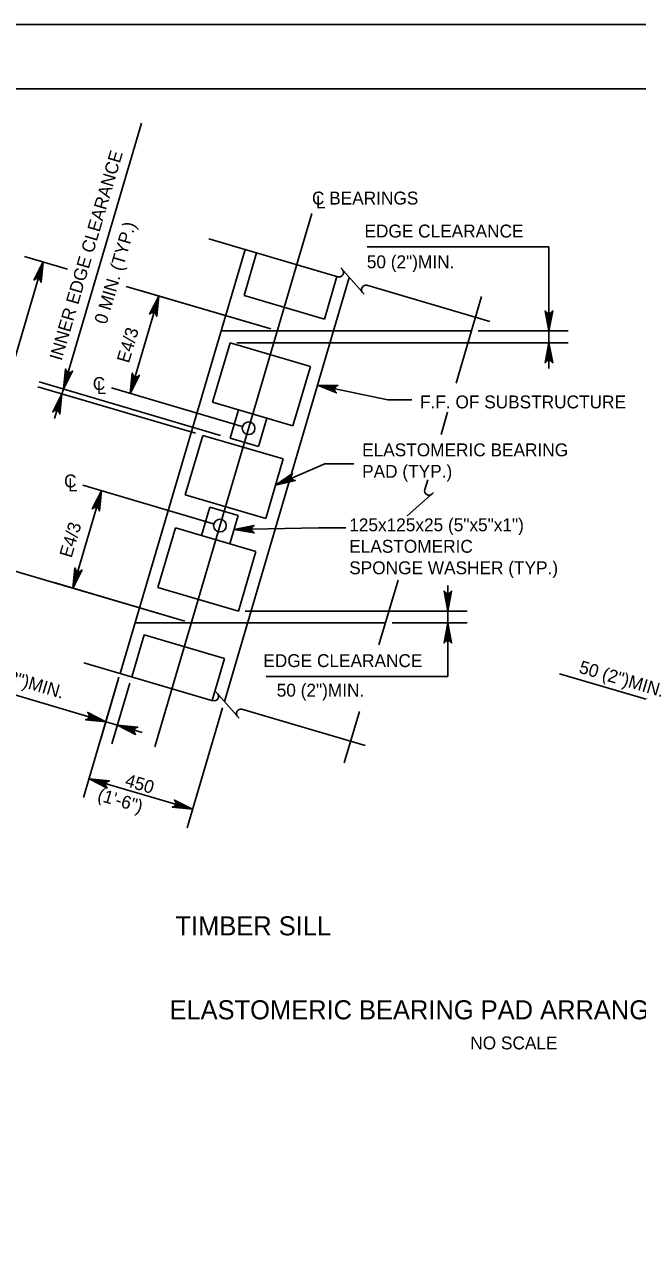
# Model space of a CAD drawing. Extents: x 638268 to 640277, y 295465 to 298435.
# Drawn here: x 639790.3 to 639932.9, y 298150.4 to 298435.5 of the extents above; entities that cross this region are included whole.
import ezdxf

# ---------------------------------------------------------------- set-up
doc = ezdxf.new("R2010")
doc.units = 0
for name, color, linetype in [('2', 7, 'Continuous'), ('3', 7, 'Continuous'), ('4', 7, 'Continuous'), ('7', 7, 'Continuous'), ('PLT-BNDY', 7, 'Continuous')]:
    doc.layers.add(name, color=color, linetype=linetype)

msp = doc.modelspace()

# ---------------------------------------------------------------- linework, layer by layer
at = {"layer": '2'}
msp.add_line((639316.46, 298420.46), (640102.46, 298420.46), dxfattribs=at)
at = {"layer": '3'}
for p, q in [((639833.22, 298385.58), (639863.23, 298376.74)), ((639812.58, 298284.45), (639841.64, 298383.1)), ((639774.66, 298312.22), (639794.68, 298380.2)), ((639800.32, 298378.54), (639790.36, 298381.47)), ((639863.93, 298378.81), (639869.34, 298372.67)), ((639847.64, 298364.6), (639814.01, 298374.5)), ((639865.89, 298376.59), (639836.83, 298277.94)), ((639869.94, 298374.77), (639898.62, 298366.32)), ((639841.42, 298372.42), (639860.11, 298366.91)), ((639896.68, 298372.12), (639890.74, 298351.98)), ((639836.06, 298364.16), (639894.33, 298364.16)), ((639838.17, 298361.4), (639856.86, 298355.9)), ((639835.93, 298339.83), (639793.74, 298352.26)), ((639830.12, 298340.34), (639793.42, 298351.16)), ((639834.09, 298347.56), (639852.79, 298342.05)), ((639840.14, 298345.77), (639846.74, 298343.83)), ((639888.77, 298345.26), (639887.23, 298340.03)), ((639831.82, 298339.84), (639850.51, 298334.34)), ((639838.19, 298339.17), (639844.8, 298337.22)), ((639884.13, 298329.51), (639883.46, 298327.24)), ((639827.74, 298326), (639846.44, 298320.49)), ((639885.52, 298326.55), (639879.39, 298321.13)), ((639833.46, 298323.12), (639840.07, 298321.17)), ((639825.47, 298318.29), (639844.17, 298312.78)), ((639831.51, 298316.51), (639838.12, 298314.56)), ((639827.62, 298296.62), (639770.34, 298313.49)), ((639877.23, 298306.11), (639872.8, 298291.07)), ((639821.39, 298304.44), (639840.09, 298298.93)), ((639816.04, 298296.18), (639874.31, 298296.18)), ((639818.15, 298293.42), (639836.84, 298287.92)), ((639804.17, 298286.93), (639834.18, 298278.09)), ((639834.87, 298280.16), (639840.28, 298274.02)), ((639840.89, 298276.12), (639869.56, 298267.67)), ((639868.25, 298275.6), (639864.71, 298263.61))]:
    msp.add_line(p, q, dxfattribs=at)
msp.add_lwpolyline([(639793.35, 298377.46), (639794.31, 298377.18), (639794.68, 298380.2)], close=True, dxfattribs=at)
for centre, start, end in [((639863.52, 298377.72), 253.588, 43.588), ((639869.75, 298373.76), 78.9166, 221.4552), ((639884.44, 298326.95), 163.588, 313.588), ((639834.47, 298279.08), 253.588, 43.588), ((639840.69, 298275.11), 78.9166, 221.4552)]:
    msp.add_arc(centre, 1.02, start, end, dxfattribs=at)
at = {"layer": '4'}
for p, q in [((639800.22, 298353.48), (639817.59, 298412.47)), ((639820.63, 298267.37), (639857.18, 298391.45)), ((639870.07, 298383.7), (639912.34, 298383.7)), ((639912.34, 298367.16), (639912.34, 298383.7)), ((639814.91, 298349.61), (639821.59, 298372.27)), ((639847.64, 298364.6), (639817.27, 298373.54)), ((639895.89, 298364.16), (639916.84, 298364.16)), ((639912.34, 298361.4), (639912.34, 298364.16)), ((639839.73, 298361.4), (639916.84, 298361.4)), ((639912.34, 298358.4), (639912.34, 298355.4)), ((639799.04, 298349.5), (639799.37, 298350.6)), ((639840.97, 298341.94), (639810.6, 298350.89)), ((639798.2, 298346.62), (639797.35, 298343.74)), ((639874.89, 298348.09), (639880.42, 298348.09)), ((639860.08, 298333.18), (639866.93, 298333.18)), ((639801.56, 298304.3), (639808.24, 298326.95)), ((639834.29, 298319.28), (639803.92, 298328.22)), ((639858.72, 298318.32), (639865.09, 298318.32)), ((639827.62, 298296.62), (639797.25, 298305.57)), ((639888.81, 298301.93), (639888.81, 298304.93)), ((639841.65, 298298.93), (639893.31, 298298.93)), ((639888.81, 298298.93), (639888.81, 298296.18)), ((639875.87, 298296.18), (639893.31, 298296.18)), ((639888.81, 298293.18), (639888.81, 298283.71)), ((639812.31, 298283.53), (639804.08, 298255.59)), ((639812.14, 298282.96), (639808, 298268.88)), ((639846.55, 298283.71), (639888.81, 298283.71)), ((639952.69, 298273.2), (639914.76, 298284.37)), ((639809.27, 298273.2), (639777.97, 298282.42)), ((639814.83, 298282.16), (639810.69, 298268.09)), ((639836.39, 298276.44), (639828.16, 298248.5)), ((639811.96, 298272.4), (639809.27, 298273.2)), ((639811.96, 298272.4), (639817.71, 298270.71)), ((639829.43, 298252.81), (639805.35, 298259.91))]:
    msp.add_line(p, q, dxfattribs=at)
for points in [[(639794.68, 298380.2), (639794.2, 298375.48), (639794.06, 298375.9), (639793.82, 298376.16), (639793.53, 298376.3), (639793.22, 298376.34), (639792.86, 298376.25), (639792.53, 298375.98), (639794.68, 298380.2), (639792.86, 298376.25), (639793.22, 298376.34), (639794.68, 298380.2), (639793.53, 298376.3), (639793.82, 298376.16), (639794.68, 298380.2), (639794.06, 298375.9)], [(639821.59, 298372.27), (639821.11, 298367.56), (639820.97, 298367.97), (639820.73, 298368.24), (639820.44, 298368.37), (639820.13, 298368.41), (639819.77, 298368.32), (639819.43, 298368.05), (639821.59, 298372.27), (639819.77, 298368.32), (639820.13, 298368.41), (639821.59, 298372.27), (639820.44, 298368.37), (639820.73, 298368.24), (639821.59, 298372.27), (639820.97, 298367.97)], [(639912.34, 298364.16), (639911.46, 298368.82), (639911.71, 298368.46), (639912.02, 298368.27), (639912.34, 298368.22), (639912.65, 298368.27), (639912.96, 298368.46), (639913.21, 298368.82), (639912.34, 298364.16), (639912.96, 298368.46), (639912.65, 298368.27), (639912.34, 298364.16), (639912.34, 298368.22), (639912.02, 298368.27), (639912.34, 298364.16), (639911.71, 298368.46)], [(639912.34, 298361.4), (639913.21, 298356.74), (639912.96, 298357.1), (639912.65, 298357.29), (639912.34, 298357.34), (639912.02, 298357.29), (639911.71, 298357.1), (639911.46, 298356.74), (639912.34, 298361.4), (639911.71, 298357.1), (639912.02, 298357.29), (639912.34, 298361.4), (639912.34, 298357.34), (639912.65, 298357.29), (639912.34, 298361.4), (639912.96, 298357.1)], [(639799.37, 298350.6), (639799.85, 298355.32), (639799.99, 298354.9), (639800.23, 298354.64), (639800.52, 298354.5), (639800.83, 298354.46), (639801.18, 298354.55), (639801.53, 298354.82), (639799.37, 298350.6), (639801.18, 298354.55), (639800.83, 298354.46), (639799.37, 298350.6), (639800.52, 298354.5), (639800.23, 298354.64), (639799.37, 298350.6), (639799.99, 298354.9)], [(639814.91, 298349.61), (639815.39, 298354.33), (639815.53, 298353.92), (639815.78, 298353.65), (639816.06, 298353.51), (639816.38, 298353.47), (639816.73, 298353.56), (639817.07, 298353.84), (639814.91, 298349.61), (639816.73, 298353.56), (639816.38, 298353.47), (639814.91, 298349.61), (639816.06, 298353.51), (639815.78, 298353.65), (639814.91, 298349.61), (639815.53, 298353.92)], [(639858.51, 298351.54), (639874.89, 298348.09)], [(639858.51, 298351.54), (639863.25, 298351.44), (639862.84, 298351.27), (639862.6, 298351), (639862.48, 298350.7), (639862.47, 298350.39), (639862.59, 298350.04), (639862.89, 298349.73), (639858.51, 298351.54), (639862.59, 298350.04), (639862.47, 298350.39), (639858.51, 298351.54), (639862.48, 298350.7), (639862.6, 298351), (639858.51, 298351.54), (639862.84, 298351.27)], [(639799.04, 298349.5), (639798.56, 298344.78), (639798.43, 298345.2), (639798.18, 298345.46), (639797.9, 298345.6), (639797.58, 298345.64), (639797.23, 298345.55), (639796.89, 298345.27), (639799.04, 298349.5), (639797.23, 298345.55), (639797.58, 298345.64), (639799.04, 298349.5), (639797.9, 298345.6), (639798.18, 298345.46), (639799.04, 298349.5), (639798.43, 298345.2)], [(639848.73, 298328.28), (639860.24, 298333.25)], [(639848.73, 298328.28), (639852.67, 298330.93), (639852.44, 298330.56), (639852.39, 298330.2), (639852.46, 298329.9), (639852.64, 298329.63), (639852.93, 298329.42), (639853.36, 298329.33), (639848.73, 298328.28), (639852.93, 298329.42), (639852.64, 298329.63), (639848.73, 298328.28), (639852.46, 298329.9), (639852.39, 298330.2), (639848.73, 298328.28), (639852.44, 298330.56)], [(639808.24, 298326.95), (639807.76, 298322.24), (639807.62, 298322.65), (639807.38, 298322.92), (639807.09, 298323.06), (639806.78, 298323.09), (639806.43, 298323), (639806.09, 298322.73), (639808.24, 298326.95), (639806.43, 298323), (639806.78, 298323.09), (639808.24, 298326.95), (639807.09, 298323.06), (639807.38, 298322.92), (639808.24, 298326.95), (639807.62, 298322.65)], [(639839.11, 298317.92), (639843.75, 298318.89), (639843.4, 298318.63), (639843.22, 298318.32), (639843.18, 298318), (639843.23, 298317.69), (639843.43, 298317.38), (639843.79, 298317.14), (639839.11, 298317.92), (639843.43, 298317.38), (639843.23, 298317.69), (639839.11, 298317.92), (639843.18, 298318), (639843.22, 298318.32), (639839.11, 298317.92), (639843.4, 298318.63)], [(639839.11, 298317.92), (639858.72, 298318.32)], [(639801.56, 298304.3), (639802.04, 298309.01), (639802.18, 298308.6), (639802.43, 298308.33), (639802.71, 298308.19), (639803.03, 298308.16), (639803.38, 298308.25), (639803.72, 298308.52), (639801.56, 298304.3), (639803.38, 298308.25), (639803.03, 298308.16), (639801.56, 298304.3), (639802.71, 298308.19), (639802.43, 298308.33), (639801.56, 298304.3), (639802.18, 298308.6)], [(639888.81, 298298.93), (639887.94, 298303.6), (639888.19, 298303.24), (639888.5, 298303.05), (639888.81, 298303), (639889.13, 298303.05), (639889.44, 298303.24), (639889.69, 298303.6), (639888.81, 298298.93), (639889.44, 298303.24), (639889.13, 298303.05), (639888.81, 298298.93), (639888.81, 298303), (639888.5, 298303.05), (639888.81, 298298.93), (639888.19, 298303.24)], [(639888.81, 298296.18), (639889.69, 298291.52), (639889.44, 298291.88), (639889.13, 298292.06), (639888.81, 298292.12), (639888.5, 298292.06), (639888.19, 298291.88), (639887.94, 298291.52), (639888.81, 298296.18), (639888.19, 298291.88), (639888.5, 298292.06), (639888.81, 298296.18), (639888.81, 298292.12), (639889.13, 298292.06), (639888.81, 298296.18), (639889.44, 298291.88)], [(639809.27, 298273.2), (639804.55, 298273.67), (639804.96, 298273.81), (639805.23, 298274.06), (639805.37, 298274.34), (639805.41, 298274.66), (639805.32, 298275.01), (639805.04, 298275.35), (639809.27, 298273.2), (639805.32, 298275.01), (639805.41, 298274.66), (639809.27, 298273.2), (639805.37, 298274.34), (639805.23, 298274.06), (639809.27, 298273.2), (639804.96, 298273.81)], [(639811.96, 298272.4), (639816.67, 298271.92), (639816.26, 298271.79), (639815.99, 298271.54), (639815.85, 298271.26), (639815.82, 298270.94), (639815.91, 298270.59), (639816.18, 298270.25), (639811.96, 298272.4), (639815.91, 298270.59), (639815.82, 298270.94), (639811.96, 298272.4), (639815.85, 298271.26), (639815.99, 298271.54), (639811.96, 298272.4), (639816.26, 298271.79)], [(639805.35, 298259.91), (639810.07, 298259.43), (639809.65, 298259.29), (639809.39, 298259.04), (639809.25, 298258.76), (639809.21, 298258.44), (639809.3, 298258.09), (639809.58, 298257.75), (639805.35, 298259.91), (639809.3, 298258.09), (639809.21, 298258.44), (639805.35, 298259.91), (639809.25, 298258.76), (639809.39, 298259.04), (639805.35, 298259.91), (639809.65, 298259.29)], [(639829.43, 298252.81), (639824.71, 298253.29), (639825.13, 298253.43), (639825.39, 298253.68), (639825.53, 298253.96), (639825.57, 298254.28), (639825.48, 298254.63), (639825.2, 298254.97), (639829.43, 298252.81), (639825.48, 298254.63), (639825.57, 298254.28), (639829.43, 298252.81), (639825.53, 298253.96), (639825.39, 298253.68), (639829.43, 298252.81), (639825.13, 298253.43)]]:
    msp.add_lwpolyline(points, dxfattribs=at)
for points in [[(639820.26, 298369.54), (639821.22, 298369.25), (639821.59, 298372.27)], [(639911.84, 298367.16), (639912.84, 298367.16), (639912.34, 298364.16)], [(639911.84, 298358.4), (639912.84, 298358.4), (639912.34, 298361.4)], [(639799.74, 298353.62), (639800.7, 298353.34), (639799.37, 298350.6)], [(639815.28, 298352.63), (639816.24, 298352.35), (639814.91, 298349.61)], [(639858.51, 298351.54), (639861.39, 298350.68), (639861.49, 298351.17)], [(639797.72, 298346.76), (639798.68, 298346.48), (639799.04, 298349.5)], [(639848.73, 298328.28), (639851.59, 298329.24), (639851.39, 298329.7)], [(639806.91, 298324.22), (639807.87, 298323.93), (639808.24, 298326.95)], [(639801.93, 298307.31), (639802.89, 298307.03), (639801.56, 298304.29)], [(639888.31, 298301.93), (639889.31, 298301.93), (639888.81, 298298.93)], [(639888.31, 298293.18), (639889.31, 298293.18), (639888.81, 298296.18)], [(639806.53, 298274.52), (639806.25, 298273.56), (639809.27, 298273.2)], [(639814.98, 298272.04), (639814.69, 298271.08), (639811.96, 298272.4)], [(639808.37, 298259.54), (639808.09, 298258.58), (639805.35, 298259.91)], [(639826.69, 298254.14), (639826.41, 298253.18), (639829.43, 298252.81)]]:
    msp.add_lwpolyline(points, close=True, dxfattribs=at)
at = {"layer": '7'}
for p, q in [((639841.42, 298372.42), (639844.33, 298382.31)), ((639860.11, 298366.91), (639863.02, 298376.8)), ((639834.09, 298347.56), (639838.17, 298361.4)), ((639852.79, 298342.05), (639856.86, 298355.9)), ((639838.19, 298339.17), (639840.14, 298345.77)), ((639844.8, 298337.22), (639846.74, 298343.83)), ((639827.74, 298326), (639831.82, 298339.84)), ((639846.44, 298320.49), (639850.51, 298334.34)), ((639831.51, 298316.51), (639833.46, 298323.12)), ((639838.12, 298314.56), (639840.07, 298321.17)), ((639821.39, 298304.44), (639825.47, 298318.29)), ((639840.09, 298298.93), (639844.17, 298312.78)), ((639815.27, 298283.66), (639818.15, 298293.42)), ((639833.97, 298278.16), (639836.84, 298287.92))]:
    msp.add_line(p, q, dxfattribs=at)
for centre in [(639842.47, 298341.5), (639835.79, 298318.84)]:
    msp.add_circle(centre, 1.48, dxfattribs=at)
at = {"layer": 'PLT-BNDY'}
msp.add_lwpolyline([(639276.46, 298435.46), (640117.46, 298435.46), (640117.46, 297841.46), (639276.46, 297841.46)], close=True, dxfattribs=at)

# ---------------------------------------------------------------- texts
at = {"layer": '3'}
for s, p in [('TIMBER SILL', (639825.46, 298223.48)), ('ELASTOMERIC BEARING PAD ARRANGEMENTS', (639824.06, 298203.94))]:
    msp.add_text(s, height=4.4292, dxfattribs=at).set_placement(p)
at = {"layer": '4'}
for s, rotation, p in [('INNER EDGE CLEARANCE', 73.588, (639798.95, 298357.05)), ('0 MIN. (TYP.)', 73.588, (639809.38, 298365.51)), ('E4/3', 73.588, (639814.62, 298356.49)), ('E4/3', 73.588, (639801.27, 298311.17)), ('50 (2")MIN.', 343.588, (639779.54, 298284.27)), ('50 (2")MIN.', 343.588, (639919.13, 298284.63)), ('450', 343.588, (639813.52, 298258.27)), ('(1\'-6")', 343.588, (639807.11, 298254.95))]:
    msp.add_text(s, height=3, rotation=rotation, dxfattribs=at).set_placement(p)
for s, p in [('C BEARINGS', (639857.21, 298393.56)), ('L', (639858.16, 298392.65)), ('EDGE CLEARANCE', (639869.42, 298385.89)), ('50 (2")MIN.', (639869.97, 298378.73)), ('C', (639806.21, 298350.39)), ('L', (639807.15, 298349.48)), ('F.F. OF SUBSTRUCTURE', (639882.35, 298346.12)), ('ELASTOMERIC BEARING', (639868.88, 298334.96)), ('PAD (TYP.)', (639868.88, 298329.96)), ('C', (639799.53, 298327.73)), ('L', (639800.48, 298326.82)), ('125x125x25 (5"x5"x1")', (639865.88, 298317.52)), ('ELASTOMERIC', (639865.88, 298312.52)), ('SPONGE WASHER (TYP.)', (639865.88, 298307.52)), ('EDGE CLEARANCE', (639845.9, 298285.91)), ('50 (2")MIN.', (639849.01, 298279.03)), ('NO SCALE', (639894.04, 298196.94))]:
    msp.add_text(s, height=3, dxfattribs=at).set_placement(p)

doc.saveas('drawing.dxf')
